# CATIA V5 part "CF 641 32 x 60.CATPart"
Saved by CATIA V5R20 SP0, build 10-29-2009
Part number: CF 641 32 x 60
Definition: NONE
Nomenclature: CF 641 32 x 60
Source: Unknown
Description: CF 641 32 x 60
Bounding box of the stored display mesh (mm): x -34 to 26, y -26.5 to 26.5, z -26.5 to 26.5
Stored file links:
  C:\Users\Utente\Desktop\IO LAVORO\3D X SITO CF\X SITO\CF 641\CF 641 32 x 60.CATPart
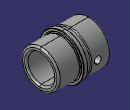
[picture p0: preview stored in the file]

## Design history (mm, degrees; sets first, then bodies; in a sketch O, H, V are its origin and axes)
Body1 "CF 641 32 x 60" (main body)
  Solid1: solid without history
